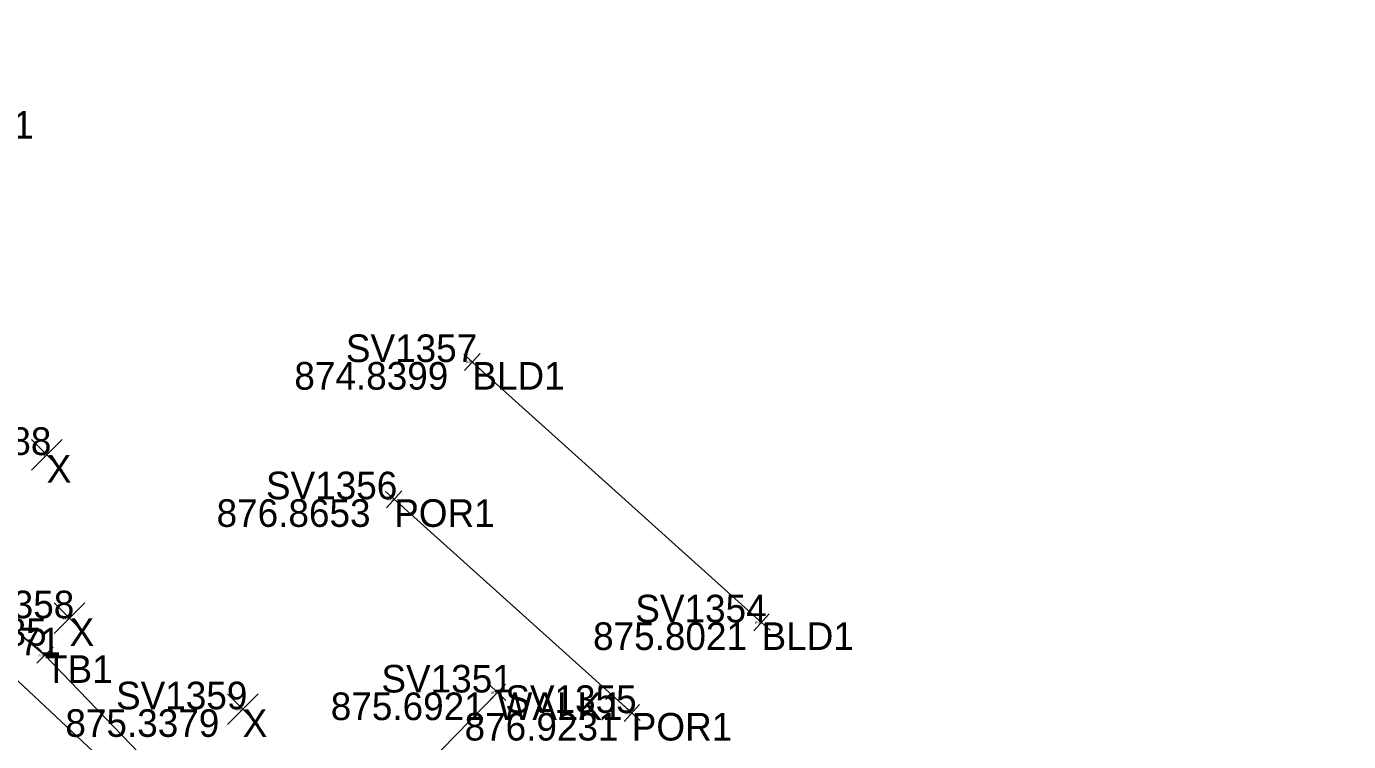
# Model space of a CAD drawing. Extents: x 1469677 to 1493262, y 375219 to 389293.
# Drawn here: x 1480162.2 to 1480219.6, y 379473.9 to 379505 of the extents above; entities that cross this region are included whole.
import ezdxf

# ---------------------------------------------------------------- set-up
doc = ezdxf.new("R2010")
doc.units = 0
for name, color, linetype in [('Border', 7, 'Continuous'), ('DV_X_Lot_Line', 7, 'Continuous'), ('DV_X_Text', 7, 'Continuous'), ('GK_Visualization', 7, 'Continuous'), ('PNTELEV', 7, 'Continuous'), ('PV_X_Curb', 7, 'Continuous'), ('RW_P_Esmt_SW', 7, 'Continuous'), ('RW_P_Esmt_U', 7, 'Continuous'), ('SV_X_Mon_Cells_Found', 7, 'Continuous'), ('UT_X_Water', 7, 'Continuous')]:
    doc.layers.add(name, color=color, linetype=linetype)

msp = doc.modelspace()

# ---------------------------------------------------------------- linework, layer by layer
at = {"layer": 'Border'}
msp.add_lwpolyline([(1480194.12, 379479.058), (1480181.546, 379490.377)], dxfattribs=at)
at = {"layer": 'DV_X_Lot_Line'}
msp.add_lwpolyline([(1480182.64, 379476.009), (1480172.384, 379465.5), (1480170.586, 379463.4)], dxfattribs=at)
at = {"layer": 'PNTELEV'}
for p, q in [((1480181.918, 379490.042), (1480181.174, 379490.712)), ((1480181.211, 379490.005), (1480181.88, 379490.749)), ((1480181.546, 379490.377), (1480181.546, 379490.377)), ((1480178.518, 379484.076), (1480177.775, 379484.745)), ((1480177.812, 379484.039), (1480178.481, 379484.782)), ((1480178.147, 379484.41), (1480178.147, 379484.41)), ((1480194.492, 379478.723), (1480193.749, 379479.392)), ((1480193.786, 379478.686), (1480194.455, 379479.429)), ((1480194.12, 379479.058), (1480194.12, 379479.058)), ((1480162.606, 379477.28), (1480163.326, 379477.973)), ((1480163.313, 379477.266), (1480162.619, 379477.987)), ((1480162.966, 379477.627), (1480162.966, 379477.627)), ((1480182.998, 379475.659), (1480182.282, 379476.358)), ((1480182.989, 379476.366), (1480182.291, 379475.651)), ((1480182.64, 379476.009), (1480182.64, 379476.009)), ((1480188.848, 379474.787), (1480188.105, 379475.455)), ((1480188.142, 379474.749), (1480188.811, 379475.493)), ((1480188.477, 379475.121), (1480188.477, 379475.121))]:
    msp.add_line(p, q, dxfattribs=at)
at = {"layer": 'PV_X_Curb'}
msp.add_lwpolyline([(1480170.345, 379463.114), (1480171.936, 379465.283), (1480168.947, 379471.416), (1480162.966, 379477.627), (1480148.764, 379489.638), (1480146.649, 379490.926), (1480144.483, 379489.446), (1480143.212, 379488.463)], dxfattribs=at)
at = {"layer": 'RW_P_Esmt_U'}
for p, q in [((1480162.374, 379485.671), (1480163.707, 379487.006)), ((1480162.374, 379487.006), (1480163.707, 379485.671)), ((1480163.37, 379478.57), (1480164.703, 379479.905)), ((1480163.37, 379479.905), (1480164.703, 379478.57)), ((1480170.896, 379474.613), (1480172.23, 379475.948)), ((1480170.896, 379475.948), (1480172.23, 379474.613))]:
    msp.add_line(p, q, dxfattribs=at)
at = {"layer": 'SV_X_Mon_Cells_Found'}
msp.add_lwpolyline([(1477206.544, 382340.781), (1479657.335, 379947.979), (1480466.338, 379191.878)], dxfattribs=at)
at = {"layer": 'UT_X_Water'}
msp.add_lwpolyline([(1480188.477, 379475.121), (1480178.147, 379484.41)], dxfattribs=at)

# ---------------------------------------------------------------- texts
at = {"layer": 'DV_X_Text'}
for s, height, p in [('874.8399', 1.2, (1480173.808, 379489.177)), ('874.84', 0.06, (1480181.266, 379490.317)), ('874.67', 0.06, (1480162.759, 379486.278)), ('876.8653', 1.2, (1480170.427, 379483.21)), ('876.87', 0.06, (1480177.866, 379484.35)), ('874.7985', 1.2, (1480156.346, 379478.037)), ('874.80', 0.06, (1480163.75, 379479.177)), ('875.8021', 1.2, (1480186.796, 379477.858)), ('875.80', 0.06, (1480193.835, 379478.998)), ('874.78', 0.06, (1480162.686, 379477.567)), ('875.6921', 1.2, (1480175.391, 379474.809)), ('875.69', 0.06, (1480182.358, 379475.949)), ('875.3379', 1.2, (1480163.853, 379474.08)), ('875.34', 0.06, (1480171.282, 379475.22)), ('876.9231', 1.2, (1480181.209, 379473.921)), ('876.92', 0.06, (1480188.195, 379475.061))]:
    msp.add_text(s, height=height, dxfattribs=at).set_placement(p)
at = {"layer": 'GK_Visualization'}
for s, p in [('POR1', (1480158.103, 379500.087)), ('BLD1', (1480181.546, 379489.177)), ('X', (1480163.041, 379485.138)), ('POR1', (1480178.147, 379483.21)), ('X', (1480164.036, 379478.037)), ('BLD1', (1480194.12, 379477.858)), ('TB1', (1480162.966, 379476.427)), ('WALK1', (1480182.64, 379474.809)), ('X', (1480171.563, 379474.08)), ('POR1', (1480188.477, 379473.921))]:
    msp.add_text(s, height=1.2, dxfattribs=at).set_placement(p)
at = {"layer": 'RW_P_Esmt_SW'}
for s, height, p in [('SV1357', 1.2, (1480176.048, 379490.377)), ('SV1357', 0.06, (1480181.271, 379490.377)), ('SV1388', 1.2, (1480157.533, 379486.338)), ('SV1388', 0.06, (1480162.766, 379486.338)), ('SV1356', 1.2, (1480172.573, 379484.41)), ('SV1356', 0.06, (1480177.868, 379484.41)), ('SV1358', 1.2, (1480158.529, 379479.237)), ('SV1354', 1.2, (1480188.631, 379479.058)), ('SV1358', 0.06, (1480163.761, 379479.237)), ('SV1371', 1.2, (1480157.938, 379477.627)), ('SV1354', 0.06, (1480193.846, 379479.058)), ('SV1371', 0.06, (1480162.715, 379477.627)), ('SV1351', 1.2, (1480177.593, 379476.009)), ('SV1359', 1.2, (1480166.055, 379475.28)), ('SV1351', 0.06, (1480182.388, 379476.009)), ('SV1355', 1.2, (1480182.979, 379475.121)), ('SV1359', 0.06, (1480171.288, 379475.28)), ('SV1355', 0.06, (1480188.202, 379475.121))]:
    msp.add_text(s, height=height, dxfattribs=at).set_placement(p)

doc.saveas('drawing.dxf')
